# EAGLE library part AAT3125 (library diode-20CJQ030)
AAT3125 USB OTG 5V Charge Pump General Description: The AAT3125 USB On-the-Go (OTG) Charge Pump is a member of AnalogicTech's Total Power Management IC product family. The device integrates a high efficiency 1.5x fractional 100mA Regulated Charge Pump for supplying VBUS with the additional functions required for OTG-devices (formerly known as Dual Role Devices). Four voltage detectors monitor VBUS and a current source, dedicated for VBUS pulsing, are provided for compliance with Session Request Protocol (SRP) as defined by the USB OTG Supplement. The charge pump section uses a high efficiency fractional topology, with a high frequency 750kHz switching speed which enables the use of small capacitors less than 3.3µF. The AAT3125 features extremely low quiescent current to extend battery run time. Additionally, the device integrates protection features such as undervoltage lockout, output short circuit and thermal protection. The AAT3125 is available in a surface mount QFN44-16 package, and is rated from -40°C to 85°C. Features: Regulated Fractional Charge Pump 100 mA Output Current Reverse Load Protection Power Good Flag SRP detection Flag SRP Ready Flag Output Short Circuit and Thermal Protection Under Voltage Protection Less than 1µA consumed while disabled Designed to allow operation with output capacitance as low as 3.3µF. 16-pin 4x4mm QFN package Applications: Cell Phones Hand Held Computers PDAs Please send any comments to: messi@users.sourceforge.net
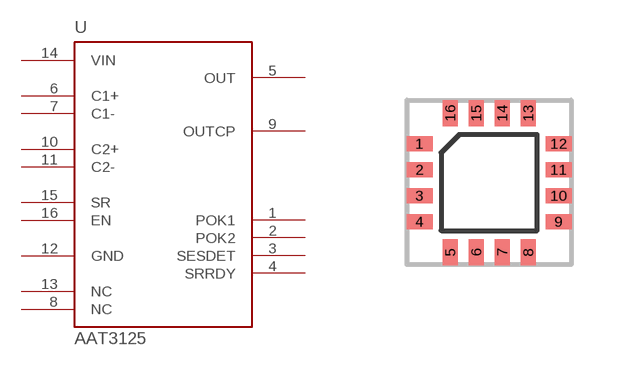
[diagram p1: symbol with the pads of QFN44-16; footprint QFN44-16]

Designator prefix U

## AAT3125  [QFN44-16]
1  POK1  out
2  POK2  out
3  SESDET  out
4  SRRDY  out
5  OUT  out
6  C1+
7  C1-
8  NC  nc
9  OUTCP  out
10  C2+
11  C2-
12  GND  pwr
13  NC  nc
14  VIN  pwr
15  SR  in
16  EN  in

## Footprint QFN44-16 (pad centres in mm)
Package for the Analogic Tech AAT3125 USB OTG 5V Charge Pump
smd 0.65 x 0.38: 1 -1.74,0.975; 2 -1.74,0.325; 3 -1.74,-0.325; 4 -1.74,-0.975; 9 1.74,-0.975; 10 1.74,-0.325; 11 1.74,0.325; 12 1.74,0.975
smd 0.38 x 0.65: 5 -0.975,-1.74; 6 -0.325,-1.74; 7 0.325,-1.74; 8 0.975,-1.74; 13 0.975,1.74; 14 0.325,1.74; 15 -0.325,1.74; 16 -0.975,1.74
